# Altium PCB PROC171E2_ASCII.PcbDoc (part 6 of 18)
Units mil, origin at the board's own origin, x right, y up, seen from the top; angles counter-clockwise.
Board outline 7700 x 2300 mil, 6 copper layers (Top Layer, GND 1, SIG 1, SIG 2, GND 2, Bottom Layer), stack 61.062 mil thick; 938 components, 688 nets, 11933 pads, 1723 vias.
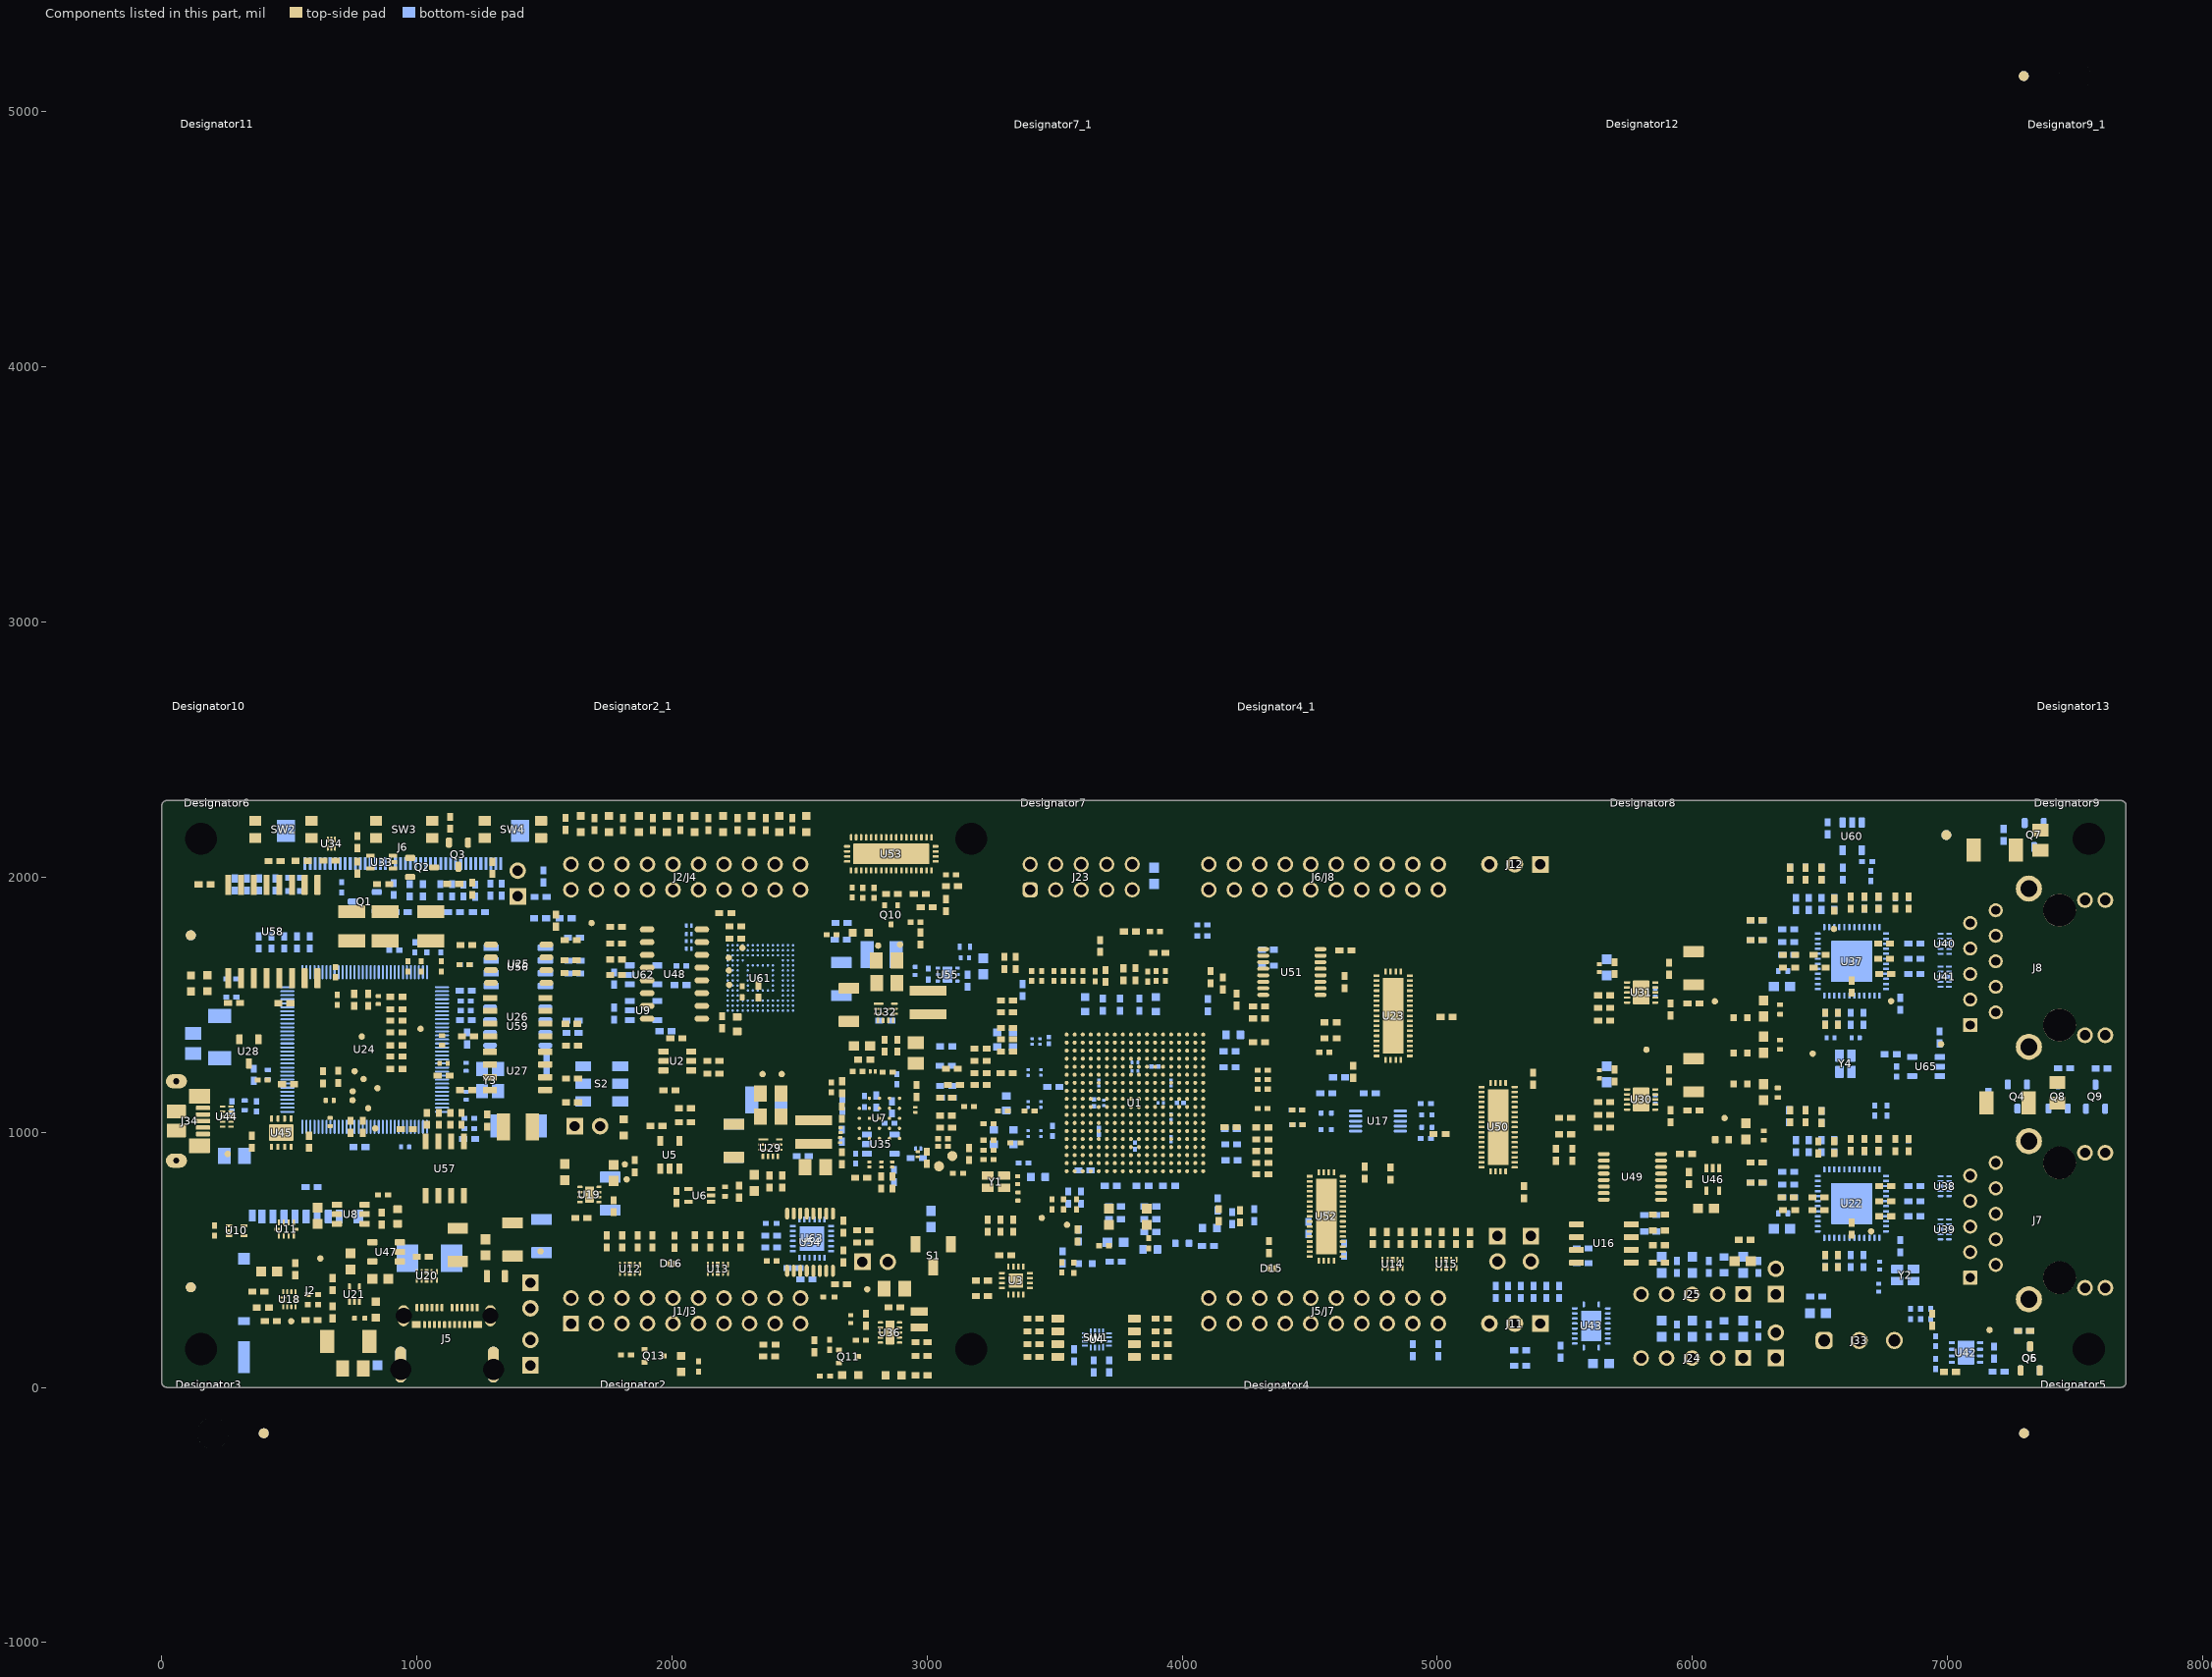
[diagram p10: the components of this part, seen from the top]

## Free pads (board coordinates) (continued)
  round 1 on Mech23: 1(4219.17,1490) 1(4219.17,1490) 1(4219.17,1570) 1(4219.17,1570) 1(4219.17,1575) 1(4219.17,1575) 1(4219.17,1585) 1(4219.17,1585) 1(4219.17,1590) 1(4219.17,1590) 1(4219.17,1670) 1(4219.17,1670) 1(4219.17,1675) 1(4219.17,1675) 1(4219.17,1685) 1(4219.17,1685) 1(4219.17,1690) 1(4219.17,1690) 1(4220.17,620) 1(4220.17,620) 1(4220.17,720) 1(4220.17,720) 1(4220.17,820) 1(4220.17,820) 1(4220.17,920) 1(4220.17,920) 1(4220.17,1020) 1(4220.17,1020) 1(4220.17,1280) 1(4220.17,1280) 1(4220.17,1380) 1(4220.17,1380) 1(4220.17,1480) 1(4220.17,1480) 1(4220.17,1580) 1(4220.17,1580) 1(4220.17,1680) 1(4220.17,1680) 1(4224.17,620) 1(4224.17,620) 1(4224.17,720) 1(4224.17,720) 1(4224.17,820) 1(4224.17,820) 1(4224.17,920) 1(4224.17,920) 1(4224.17,1020) 1(4224.17,1020) 1(4224.17,1280) 1(4224.17,1280) 1(4224.17,1380) 1(4224.17,1380) 1(4224.17,1480) 1(4224.17,1480) 1(4224.17,1580) 1(4224.17,1580) 1(4224.17,1680) 1(4224.17,1680) 1(4294.17,240) 1(4294.17,240) 1(4294.17,260) 1(4294.17,260) 1(4294.17,340) 1(4294.17,340) 1(4294.17,360) 1(4294.17,360) 1(4294.17,1940) 1(4294.17,1940) 1(4294.17,1960) 1(4294.17,1960) 1(4294.17,2040) 1(4294.17,2040) 1(4294.17,2060) 1(4294.17,2060) 1(4298.17,244) 1(4298.17,244) 1(4298.17,256) 1(4298.17,256) 1(4298.17,344) 1(4298.17,344) 1(4298.17,356) 1(4298.17,356) 1(4298.17,1944) 1(4298.17,1944) 1(4298.17,1956) 1(4298.17,1956) 1(4298.17,2044) 1(4298.17,2044) 1(4298.17,2056) 1(4298.17,2056) 1(4310.17,244) 1(4310.17,244) 1(4310.17,256) 1(4310.17,256) 1(4310.17,344) 1(4310.17,344) 1(4310.17,356) 1(4310.17,356) 1(4310.17,1944) 1(4310.17,1944) 1(4310.17,1956) 1(4310.17,1956) 1(4310.17,2044) 1(4310.17,2044) 1(4310.17,2056) 1(4310.17,2056) 1(4314.17,240) 1(4314.17,240) 1(4314.17,260) 1(4314.17,260) 1(4314.17,340) 1(4314.17,340) 1(4314.17,360) 1(4314.17,360) 1(4314.17,1940) 1(4314.17,1940) 1(4314.17,1960) 1(4314.17,1960) 1(4314.17,2040) 1(4314.17,2040) 1(4314.17,2060) 1(4314.17,2060) 1(4329.17,1080) 1(4329.17,1084) 1(4329.17,1096) 1(4329.17,1100) 1(4339.17,620) 1(4339.17,620) 1(4339.17,720) 1(4339.17,720) 1(4339.17,820) 1(4339.17,820) 1(4339.17,920) 1(4339.17,920) 1(4339.17,1020) 1(4339.17,1020) 1(4339.17,1280) 1(4339.17,1280) 1(4339.17,1380) 1(4339.17,1380) 1(4339.17,1480) 1(4339.17,1480) 1(4339.17,1580) 1(4339.17,1580) 1(4339.17,1680) 1(4339.17,1680) 1(4343.17,620) 1(4343.17,620) 1(4343.17,720) 1(4343.17,720) 1(4343.17,820) 1(4343.17,820) 1(4343.17,920) 1(4343.17,920) 1(4343.17,1020) 1(4343.17,1020) 1(4343.17,1280) 1(4343.17,1280) 1(4343.17,1380) 1(4343.17,1380) 1(4343.17,1480) 1(4343.17,1480) 1(4343.17,1580) 1(4343.17,1580) 1(4343.17,1680) 1(4343.17,1680) 1(4344.17,610) 1(4344.17,610) 1(4344.17,615) 1(4344.17,615) 1(4344.17,625) 1(4344.17,625) 1(4344.17,630) 1(4344.17,630) 1(4344.17,710) 1(4344.17,710) 1(4344.17,715) 1(4344.17,715) 1(4344.17,725) 1(4344.17,725) 1(4344.17,730) 1(4344.17,730) 1(4344.17,810) 1(4344.17,810) 1(4344.17,815) 1(4344.17,815) 1(4344.17,825) 1(4344.17,825) 1(4344.17,830) 1(4344.17,830) 1(4344.17,910) 1(4344.17,910) 1(4344.17,915) 1(4344.17,915) 1(4344.17,925) 1(4344.17,925) 1(4344.17,930) 1(4344.17,930) 1(4344.17,1010) 1(4344.17,1010) 1(4344.17,1015) 1(4344.17,1015) 1(4344.17,1025) 1(4344.17,1025) 1(4344.17,1030) 1(4344.17,1030) 1(4344.17,1270) 1(4344.17,1270) 1(4344.17,1275) 1(4344.17,1275) 1(4344.17,1285) 1(4344.17,1285) 1(4344.17,1290) 1(4344.17,1290) 1(4344.17,1370) 1(4344.17,1370) 1(4344.17,1375) 1(4344.17,1375) 1(4344.17,1385) 1(4344.17,1385) 1(4344.17,1390) 1(4344.17,1390) 1(4344.17,1470) 1(4344.17,1470) 1(4344.17,1475) 1(4344.17,1475) 1(4344.17,1485) 1(4344.17,1485) 1(4344.17,1490) 1(4344.17,1490) 1(4344.17,1570) 1(4344.17,1570) 1(4344.17,1575) 1(4344.17,1575) 1(4344.17,1585) 1(4344.17,1585) 1(4344.17,1590) 1(4344.17,1590) 1(4344.17,1670) 1(4344.17,1670) 1(4344.17,1675) 1(4344.17,1675) 1(4344.17,1685) 1(4344.17,1685) 1(4344.17,1690) 1(4344.17,1690) 1(4346.17,614) 1(4346.17,614) 1(4346.17,617) 1(4346.17,617) 1(4346.17,623) 1(4346.17,623) 1(4346.17,626) 1(4346.17,626) 1(4346.17,714) 1(4346.17,714) 1(4346.17,717) 1(4346.17,717) 1(4346.17,723) 1(4346.17,723) 1(4346.17,726) 1(4346.17,726) 1(4346.17,814) 1(4346.17,814) 1(4346.17,817) 1(4346.17,817) 1(4346.17,823) 1(4346.17,823) 1(4346.17,826) 1(4346.17,826) 1(4346.17,914) 1(4346.17,914) 1(4346.17,917) 1(4346.17,917) 1(4346.17,923) 1(4346.17,923) 1(4346.17,926) 1(4346.17,926) 1(4346.17,1014) 1(4346.17,1014) 1(4346.17,1017) 1(4346.17,1017) 1(4346.17,1023) 1(4346.17,1023) 1(4346.17,1026) 1(4346.17,1026) 1(4346.17,1274) 1(4346.17,1274) 1(4346.17,1277) 1(4346.17,1277) 1(4346.17,1283) 1(4346.17,1283) 1(4346.17,1286) 1(4346.17,1286) 1(4346.17,1374) 1(4346.17,1374) 1(4346.17,1377) 1(4346.17,1377) 1(4346.17,1383) 1(4346.17,1383) 1(4346.17,1386) 1(4346.17,1386) 1(4346.17,1474) 1(4346.17,1474) 1(4346.17,1477) 1(4346.17,1477) 1(4346.17,1483) 1(4346.17,1483) 1(4346.17,1486) 1(4346.17,1486) 1(4346.17,1574) 1(4346.17,1574) 1(4346.17,1577) 1(4346.17,1577) 1(4346.17,1583) 1(4346.17,1583) 1(4346.17,1586) 1(4346.17,1586) 1(4346.17,1674) 1(4346.17,1674) 1(4346.17,1677) 1(4346.17,1677) 1(4346.17,1683) 1(4346.17,1683) 1(4346.17,1686) 1(4346.17,1686) 1(4349.17,615) 1(4349.17,615) 1(4349.17,617) 1(4349.17,617) 1(4349.17,623) 1(4349.17,623) 1(4349.17,625) 1(4349.17,625) 1(4349.17,715) 1(4349.17,715) 1(4349.17,717) 1(4349.17,717) 1(4349.17,723) 1(4349.17,723) 1(4349.17,725) 1(4349.17,725) 1(4349.17,815) 1(4349.17,815) 1(4349.17,817) 1(4349.17,817) 1(4349.17,823) 1(4349.17,823) 1(4349.17,825) 1(4349.17,825) 1(4349.17,915) 1(4349.17,915) 1(4349.17,917) 1(4349.17,917) 1(4349.17,923) 1(4349.17,923) 1(4349.17,925) 1(4349.17,925) 1(4349.17,1015) 1(4349.17,1015) 1(4349.17,1017) 1(4349.17,1017) 1(4349.17,1023) 1(4349.17,1023) 1(4349.17,1025) 1(4349.17,1025) 1(4349.17,1275) 1(4349.17,1275) 1(4349.17,1277) 1(4349.17,1277) 1(4349.17,1283) 1(4349.17,1283) 1(4349.17,1285) 1(4349.17,1285) 1(4349.17,1375) 1(4349.17,1375) 1(4349.17,1377) 1(4349.17,1377) 1(4349.17,1383) 1(4349.17,1383) 1(4349.17,1385) 1(4349.17,1385) 1(4349.17,1475) 1(4349.17,1475) 1(4349.17,1477) 1(4349.17,1477) 1(4349.17,1483) 1(4349.17,1483) 1(4349.17,1485) 1(4349.17,1485) 1(4349.17,1575) 1(4349.17,1575) 1(4349.17,1577) 1(4349.17,1577) 1(4349.17,1583) 1(4349.17,1583) 1(4349.17,1585) 1(4349.17,1585) 1(4349.17,1675) 1(4349.17,1675) 1(4349.17,1677) 1(4349.17,1677) 1(4349.17,1683) 1(4349.17,1683) 1(4349.17,1685) 1(4349.17,1685) 1(4352.17,614) 1(4352.17,614) 1(4352.17,617) 1(4352.17,617) 1(4352.17,623) 1(4352.17,623) 1(4352.17,626) 1(4352.17,626) 1(4352.17,714) 1(4352.17,714) 1(4352.17,717) 1(4352.17,717) 1(4352.17,723) 1(4352.17,723) 1(4352.17,726) 1(4352.17,726) 1(4352.17,814) 1(4352.17,814) 1(4352.17,817) 1(4352.17,817) 1(4352.17,823) 1(4352.17,823) 1(4352.17,826) 1(4352.17,826) 1(4352.17,914) 1(4352.17,914) 1(4352.17,917) 1(4352.17,917) 1(4352.17,923) 1(4352.17,923) 1(4352.17,926) 1(4352.17,926) 1(4352.17,1014) 1(4352.17,1014) 1(4352.17,1017) 1(4352.17,1017) 1(4352.17,1023) 1(4352.17,1023) 1(4352.17,1026) 1(4352.17,1026) 1(4352.17,1274) 1(4352.17,1274) 1(4352.17,1277) 1(4352.17,1277) 1(4352.17,1283) 1(4352.17,1283) 1(4352.17,1286) 1(4352.17,1286) 1(4352.17,1374) 1(4352.17,1374) 1(4352.17,1377) 1(4352.17,1377) 1(4352.17,1383) 1(4352.17,1383) 1(4352.17,1386) 1(4352.17,1386) 1(4352.17,1474) 1(4352.17,1474) 1(4352.17,1477) 1(4352.17,1477) 1(4352.17,1483) 1(4352.17,1483) 1(4352.17,1486) 1(4352.17,1486) 1(4352.17,1574) 1(4352.17,1574) 1(4352.17,1577) 1(4352.17,1577) 1(4352.17,1583) 1(4352.17,1583) 1(4352.17,1586) 1(4352.17,1586) 1(4352.17,1674) 1(4352.17,1674) 1(4352.17,1677) 1(4352.17,1677) 1(4352.17,1683) 1(4352.17,1683) 1(4352.17,1686) 1(4352.17,1686) 1(4354.17,610) 1(4354.17,610) 1(4354.17,615) 1(4354.17,615) 1(4354.17,625) 1(4354.17,625) 1(4354.17,630) 1(4354.17,630) 1(4354.17,710) 1(4354.17,710) 1(4354.17,715) 1(4354.17,715) 1(4354.17,725) 1(4354.17,725) 1(4354.17,730) 1(4354.17,730) 1(4354.17,810) 1(4354.17,810) 1(4354.17,815) 1(4354.17,815) 1(4354.17,825) 1(4354.17,825) 1(4354.17,830) 1(4354.17,830) 1(4354.17,910) 1(4354.17,910) 1(4354.17,915) 1(4354.17,915) 1(4354.17,925) 1(4354.17,925) 1(4354.17,930) 1(4354.17,930) 1(4354.17,1010) 1(4354.17,1010) 1(4354.17,1015) 1(4354.17,1015) 1(4354.17,1025) 1(4354.17,1025) 1(4354.17,1030) 1(4354.17,1030) 1(4354.17,1270) 1(4354.17,1270) 1(4354.17,1275) 1(4354.17,1275) 1(4354.17,1285) 1(4354.17,1285) 1(4354.17,1290) 1(4354.17,1290) 1(4354.17,1370) 1(4354.17,1370) 1(4354.17,1375) 1(4354.17,1375) 1(4354.17,1385) 1(4354.17,1385) 1(4354.17,1390) 1(4354.17,1390) 1(4354.17,1470) 1(4354.17,1470) 1(4354.17,1475) 1(4354.17,1475) 1(4354.17,1485) 1(4354.17,1485) 1(4354.17,1490) 1(4354.17,1490) 1(4354.17,1570) 1(4354.17,1570) 1(4354.17,1575) 1(4354.17,1575) 1(4354.17,1585) 1(4354.17,1585) 1(4354.17,1590) 1(4354.17,1590) 1(4354.17,1670) 1(4354.17,1670) 1(4354.17,1675) 1(4354.17,1675) 1(4354.17,1685) 1(4354.17,1685) 1(4354.17,1690) 1(4354.17,1690) 1(4355.17,620) 1(4355.17,620) 1(4355.17,720) 1(4355.17,720) 1(4355.17,820) 1(4355.17,820) 1(4355.17,920) 1(4355.17,920) 1(4355.17,1020) 1(4355.17,1020) 1(4355.17,1280) 1(4355.17,1280) 1(4355.17,1380) 1(4355.17,1380) 1(4355.17,1480) 1(4355.17,1480) 1(4355.17,1580) 1(4355.17,1580) 1(4355.17,1680) 1(4355.17,1680) 1(4359.17,620) 1(4359.17,620) 1(4359.17,720) 1(4359.17,720) 1(4359.17,820) 1(4359.17,820) 1(4359.17,920) 1(4359.17,920) 1(4359.17,1020) 1(4359.17,1020) 1(4359.17,1280) 1(4359.17,1280) 1(4359.17,1380) 1(4359.17,1380) 1(4359.17,1480) 1(4359.17,1480) 1(4359.17,1580) 1(4359.17,1580) 1(4359.17,1680) 1(4359.17,1680) 1(4364.17,2240) 1(4364.17,2244) 1(4364.17,2256) 1(4364.17,2260) 1(4394.17,61.38) 1(4394.17,65.38) 1(4394.17,77.38) 1(4394.17,81.38) 1(4394.17,240) 1(4394.17,240) 1(4394.17,260) 1(4394.17,260) 1(4394.17,340) 1(4394.17,340) 1(4394.17,360) 1(4394.17,360) 1(4394.17,1940) 1(4394.17,1940) 1(4394.17,1960) 1(4394.17,1960) 1(4394.17,2040) 1(4394.17,2040) 1(4394.17,2060) 1(4394.17,2060) 1(4396.26,477.39) 1(4396.26,477.39) 1(4396.26,497.39) 1(4396.26,497.39) 1(4398.17,244) 1(4398.17,244) 1(4398.17,256) 1(4398.17,256) 1(4398.17,344) 1(4398.17,344) 1(4398.17,356) 1(4398.17,356) 1(4398.17,1944) 1(4398.17,1944) 1(4398.17,1956) 1(4398.17,1956) 1(4398.17,2044) 1(4398.17,2044) 1(4398.17,2056) 1(4398.17,2056) 1(4400.26,481.39) 1(4400.26,481.39) 1(4400.26,493.39) 1(4400.26,493.39) 1(4401.26,487.39) 1(4401.26,487.39) 1(4403.26,487.39) 1(4403.26,487.39) 1(4404.17,1805) 1(4404.17,1805) 1(4404.17,1825) 1(4404.17,1825) 1(4406.26,482.39) 1(4406.26,482.39) 1(4406.26,484.39) 1(4406.26,484.39) 1(4406.26,490.39) 1(4406.26,490.39) 1(4406.26,492.39) 1(4406.26,492.39) 1(4408.17,1809) 1(4408.17,1809) 1(4408.17,1821) 1(4408.17,1821) 1(4409.17,1815) 1(4409.17,1815) 1(4409.26,487.39) 1(4409.26,487.39) 1(4410.17,244) 1(4410.17,244) 1(4410.17,256) 1(4410.17,256) 1(4410.17,344) 1(4410.17,344) 1(4410.17,356) 1(4410.17,356) 1(4410.17,1944) 1(4410.17,1944) 1(4410.17,1956) 1(4410.17,1956) 1(4410.17,2044) 1(4410.17,2044) 1(4410.17,2056) 1(4410.17,2056) 1(4411.17,1815) 1(4411.17,1815) 1(4411.26,487.39) 1(4411.26,487.39) 1(4412.26,481.39) 1(4412.26,481.39) 1(4412.26,493.39) 1(4412.26,493.39) 1(4414.17,240) 1(4414.17,240) 1(4414.17,260) 1(4414.17,260) 1(4414.17,340) 1(4414.17,340) 1(4414.17,360) 1(4414.17,360) 1(4414.17,1810) 1(4414.17,1810) 1(4414.17,1812) 1(4414.17,1812) 1(4414.17,1818) 1(4414.17,1818) 1(4414.17,1820) 1(4414.17,1820) 1(4414.17,1940) 1(4414.17,1940) 1(4414.17,1960) 1(4414.17,1960) 1(4414.17,2040) 1(4414.17,2040) 1(4414.17,2060) 1(4414.17,2060) 1(4416.26,477.39) 1(4416.26,477.39) 1(4416.26,497.39) 1(4416.26,497.39) 1(4417.17,1815) 1(4417.17,1815) 1(4419.17,-116.65) 1(4419.17,-116.65) 1(4419.17,-96.65) 1(4419.17,-96.65) 1(4419.17,1815) 1(4419.17,1815) 1(4420.17,1809) 1(4420.17,1809) 1(4420.17,1821) 1(4420.17,1821) 1(4423.17,-112.65) 1(4423.17,-112.65) 1(4423.17,-100.65) 1(4423.17,-100.65) 1(4424.17,-106.65) 1(4424.17,-106.65) 1(4424.17,1805) 1(4424.17,1805) 1(4424.17,1825) 1(4424.17,1825) 1(4426.17,-106.65) 1(4426.17,-106.65) 1(4429.17,-111.65) 1(4429.17,-111.65) 1(4429.17,-109.65) 1(4429.17,-109.65) 1(4429.17,-103.65) 1(4429.17,-103.65) 1(4429.17,-101.65) 1(4429.17,-101.65) 1(4432.17,-106.65) 1(4432.17,-106.65) 1(4434.17,-106.65) 1(4434.17,-106.65) 1(4435.17,-112.65) 1(4435.17,-112.65) 1(4435.17,-100.65) 1(4435.17,-100.65) 1(4439.17,-116.65) 1(4439.17,-116.65) 1(4439.17,-96.65) 1(4439.17,-96.65) 1(4474.17,620) 1(4474.17,620) 1(4474.17,720) 1(4474.17,720) 1(4474.17,820) 1(4474.17,820) 1(4474.17,920) 1(4474.17,920) 1(4474.17,1020) 1(4474.17,1020) 1(4474.17,1280) 1(4474.17,1280) 1(4474.17,1380) 1(4474.17,1380) 1(4474.17,1480) 1(4474.17,1480) 1(4474.17,1580) 1(4474.17,1580) 1(4474.17,1680) 1(4474.17,1680) 1(4478.17,620) 1(4478.17,620) 1(4478.17,720) 1(4478.17,720) 1(4478.17,820) 1(4478.17,820) 1(4478.17,920) 1(4478.17,920) 1(4478.17,1020) 1(4478.17,1020) 1(4478.17,1280) 1(4478.17,1280) 1(4478.17,1380) 1(4478.17,1380) 1(4478.17,1480) 1(4478.17,1480) 1(4478.17,1580) 1(4478.17,1580) 1(4478.17,1680) 1(4478.17,1680) 1(4479.17,610) 1(4479.17,610) 1(4479.17,615) 1(4479.17,615) 1(4479.17,625) 1(4479.17,625) 1(4479.17,630) 1(4479.17,630) 1(4479.17,710) 1(4479.17,710) 1(4479.17,715) 1(4479.17,715) 1(4479.17,725) 1(4479.17,725) 1(4479.17,730) 1(4479.17,730) 1(4479.17,810) 1(4479.17,810) 1(4479.17,815) 1(4479.17,815) 1(4479.17,825) 1(4479.17,825) 1(4479.17,830) 1(4479.17,830) 1(4479.17,910) 1(4479.17,910) 1(4479.17,915) 1(4479.17,915) 1(4479.17,925) 1(4479.17,925) 1(4479.17,930) 1(4479.17,930) 1(4479.17,1010) 1(4479.17,1010) 1(4479.17,1015) 1(4479.17,1015) 1(4479.17,1025) 1(4479.17,1025) 1(4479.17,1030) 1(4479.17,1030) 1(4479.17,1270) 1(4479.17,1270) 1(4479.17,1275) 1(4479.17,1275) 1(4479.17,1285) 1(4479.17,1285) 1(4479.17,1290) 1(4479.17,1290) 1(4479.17,1370) 1(4479.17,1370) 1(4479.17,1375) 1(4479.17,1375) 1(4479.17,1385) 1(4479.17,1385) 1(4479.17,1390) 1(4479.17,1390) 1(4479.17,1470) 1(4479.17,1470) 1(4479.17,1475) 1(4479.17,1475) 1(4479.17,1485) 1(4479.17,1485) 1(4479.17,1490) 1(4479.17,1490) 1(4479.17,1570) 1(4479.17,1570) 1(4479.17,1575) 1(4479.17,1575) 1(4479.17,1585) 1(4479.17,1585) 1(4479.17,1590) 1(4479.17,1590) 1(4479.17,1670) 1(4479.17,1670) 1(4479.17,1675) 1(4479.17,1675) 1(4479.17,1685) 1(4479.17,1685) 1(4479.17,1690) 1(4479.17,1690) 1(4481.17,614) 1(4481.17,614) 1(4481.17,617) 1(4481.17,617) 1(4481.17,623) 1(4481.17,623) 1(4481.17,626) 1(4481.17,626) 1(4481.17,714) 1(4481.17,714) 1(4481.17,717) 1(4481.17,717) 1(4481.17,723) 1(4481.17,723) 1(4481.17,726) 1(4481.17,726) 1(4481.17,814) 1(4481.17,814) 1(4481.17,817) 1(4481.17,817) 1(4481.17,823) 1(4481.17,823) 1(4481.17,826) 1(4481.17,826) 1(4481.17,914) 1(4481.17,914) 1(4481.17,917) 1(4481.17,917) 1(4481.17,923) 1(4481.17,923) 1(4481.17,926) 1(4481.17,926) 1(4481.17,1014) 1(4481.17,1014) 1(4481.17,1017) 1(4481.17,1017) 1(4481.17,1023) 1(4481.17,1023) 1(4481.17,1026) 1(4481.17,1026) 1(4481.17,1274) 1(4481.17,1274) 1(4481.17,1277) 1(4481.17,1277) 1(4481.17,1283) 1(4481.17,1283) 1(4481.17,1286) 1(4481.17,1286) 1(4481.17,1374) 1(4481.17,1374) 1(4481.17,1377) 1(4481.17,1377) 1(4481.17,1383) 1(4481.17,1383) 1(4481.17,1386) 1(4481.17,1386) 1(4481.17,1474) 1(4481.17,1474) 1(4481.17,1477) 1(4481.17,1477) 1(4481.17,1483) 1(4481.17,1483) 1(4481.17,1486) 1(4481.17,1486) 1(4481.17,1574) 1(4481.17,1574) 1(4481.17,1577) 1(4481.17,1577) 1(4481.17,1583) 1(4481.17,1583) 1(4481.17,1586) 1(4481.17,1586) 1(4481.17,1674) 1(4481.17,1674) 1(4481.17,1677) 1(4481.17,1677) 1(4481.17,1683) 1(4481.17,1683) 1(4481.17,1686) 1(4481.17,1686) 1(4484.17,615) 1(4484.17,615) 1(4484.17,617) 1(4484.17,617) 1(4484.17,623) 1(4484.17,623) 1(4484.17,625) 1(4484.17,625) 1(4484.17,715) 1(4484.17,715) 1(4484.17,717) 1(4484.17,717) 1(4484.17,723) 1(4484.17,723) 1(4484.17,725) 1(4484.17,725) 1(4484.17,815) 1(4484.17,815) 1(4484.17,817) 1(4484.17,817) 1(4484.17,823) 1(4484.17,823) 1(4484.17,825) 1(4484.17,825) 1(4484.17,915) 1(4484.17,915) 1(4484.17,917) 1(4484.17,917) 1(4484.17,923) 1(4484.17,923) 1(4484.17,925) 1(4484.17,925) 1(4484.17,1015) 1(4484.17,1015) 1(4484.17,1017) 1(4484.17,1017) 1(4484.17,1023) 1(4484.17,1023) 1(4484.17,1025) 1(4484.17,1025) 1(4484.17,1275) 1(4484.17,1275) 1(4484.17,1277) 1(4484.17,1277) 1(4484.17,1283) 1(4484.17,1283) 1(4484.17,1285) 1(4484.17,1285) 1(4484.17,1375) 1(4484.17,1375) 1(4484.17,1377) 1(4484.17,1377) 1(4484.17,1383) 1(4484.17,1383) 1(4484.17,1385) 1(4484.17,1385) 1(4484.17,1475) 1(4484.17,1475) 1(4484.17,1477) 1(4484.17,1477) 1(4484.17,1483) 1(4484.17,1483) 1(4484.17,1485) 1(4484.17,1485) 1(4484.17,1575) 1(4484.17,1575) 1(4484.17,1577) 1(4484.17,1577) 1(4484.17,1583) 1(4484.17,1583) 1(4484.17,1585) 1(4484.17,1585) 1(4484.17,1675) 1(4484.17,1675) 1(4484.17,1677) 1(4484.17,1677) 1(4484.17,1683) 1(4484.17,1683) 1(4484.17,1685) 1(4484.17,1685) 1(4487.17,614) 1(4487.17,614) 1(4487.17,617) 1(4487.17,617) 1(4487.17,623) 1(4487.17,623) 1(4487.17,626) 1(4487.17,626) 1(4487.17,714) 1(4487.17,714) 1(4487.17,717) 1(4487.17,717) 1(4487.17,723) 1(4487.17,723) 1(4487.17,726) 1(4487.17,726) 1(4487.17,814) 1(4487.17,814) 1(4487.17,817) 1(4487.17,817) 1(4487.17,823) 1(4487.17,823) 1(4487.17,826) 1(4487.17,826) 1(4487.17,914) 1(4487.17,914) 1(4487.17,917) 1(4487.17,917) 1(4487.17,923) 1(4487.17,923) 1(4487.17,926) 1(4487.17,926) 1(4487.17,1014) 1(4487.17,1014) 1(4487.17,1017) 1(4487.17,1017) 1(4487.17,1023) 1(4487.17,1023) 1(4487.17,1026) 1(4487.17,1026) 1(4487.17,1274) 1(4487.17,1274) 1(4487.17,1277) 1(4487.17,1277) 1(4487.17,1283) 1(4487.17,1283) 1(4487.17,1286) 1(4487.17,1286) 1(4487.17,1374) 1(4487.17,1374) 1(4487.17,1377) 1(4487.17,1377) 1(4487.17,1383) 1(4487.17,1383) 1(4487.17,1386) 1(4487.17,1386) 1(4487.17,1474) 1(4487.17,1474) 1(4487.17,1477) 1(4487.17,1477) 1(4487.17,1483) 1(4487.17,1483) 1(4487.17,1486) 1(4487.17,1486) 1(4487.17,1574) 1(4487.17,1574) 1(4487.17,1577) 1(4487.17,1577) 1(4487.17,1583) 1(4487.17,1583) 1(4487.17,1586) 1(4487.17,1586) 1(4487.17,1674) 1(4487.17,1674) 1(4487.17,1677) 1(4487.17,1677) 1(4487.17,1683) 1(4487.17,1683) 1(4487.17,1686) 1(4487.17,1686) 1(4489.17,610) 1(4489.17,610) 1(4489.17,615) 1(4489.17,615) 1(4489.17,625) 1(4489.17,625) 1(4489.17,630) 1(4489.17,630) 1(4489.17,710) 1(4489.17,710) 1(4489.17,715) 1(4489.17,715) 1(4489.17,725) 1(4489.17,725) 1(4489.17,730) 1(4489.17,730) 1(4489.17,810) 1(4489.17,810) 1(4489.17,815) 1(4489.17,815) 1(4489.17,825) 1(4489.17,825) 1(4489.17,830) 1(4489.17,830) 1(4489.17,910) 1(4489.17,910) 1(4489.17,915) 1(4489.17,915) 1(4489.17,925) 1(4489.17,925) 1(4489.17,930) 1(4489.17,930) 1(4489.17,1010) 1(4489.17,1010) 1(4489.17,1015) 1(4489.17,1015) 1(4489.17,1025) 1(4489.17,1025) 1(4489.17,1030) 1(4489.17,1030) 1(4489.17,1270) 1(4489.17,1270) 1(4489.17,1275) 1(4489.17,1275) 1(4489.17,1285) 1(4489.17,1285) 1(4489.17,1290) 1(4489.17,1290) 1(4489.17,1370) 1(4489.17,1370) 1(4489.17,1375) 1(4489.17,1375) 1(4489.17,1385) 1(4489.17,1385) 1(4489.17,1390) 1(4489.17,1390) 1(4489.17,1470) 1(4489.17,1470) 1(4489.17,1475) 1(4489.17,1475) 1(4489.17,1485) 1(4489.17,1485) 1(4489.17,1490) 1(4489.17,1490) 1(4489.17,1570) 1(4489.17,1570) 1(4489.17,1575) 1(4489.17,1575) 1(4489.17,1585) 1(4489.17,1585) 1(4489.17,1590) 1(4489.17,1590) 1(4489.17,1670) 1(4489.17,1670) 1(4489.17,1675) 1(4489.17,1675) 1(4489.17,1685) 1(4489.17,1685) 1(4489.17,1690) 1(4489.17,1690) 1(4490.17,620) 1(4490.17,620) 1(4490.17,720) 1(4490.17,720) 1(4490.17,820) 1(4490.17,820) 1(4490.17,920) 1(4490.17,920) 1(4490.17,1020) 1(4490.17,1020) 1(4490.17,1280) 1(4490.17,1280) 1(4490.17,1380) 1(4490.17,1380) 1(4490.17,1480) 1(4490.17,1480) 1(4490.17,1580) 1(4490.17,1580) 1(4490.17,1680) 1(4490.17,1680) 1(4494.17,240) 1(4494.17,240) 1(4494.17,260) 1(4494.17,260) 1(4494.17,340) 1(4494.17,340) 1(4494.17,360) 1(4494.17,360) 1(4494.17,620) 1(4494.17,620) 1(4494.17,720) 1(4494.17,720) 1(4494.17,820) 1(4494.17,820) 1(4494.17,920) 1(4494.17,920) 1(4494.17,1020) 1(4494.17,1020) 1(4494.17,1280) 1(4494.17,1280) 1(4494.17,1380) 1(4494.17,1380) 1(4494.17,1480) 1(4494.17,1480) 1(4494.17,1580) 1(4494.17,1580) 1(4494.17,1680) 1(4494.17,1680) 1(4494.17,1940) 1(4494.17,1940) 1(4494.17,1960) 1(4494.17,1960) 1(4494.17,2040) 1(4494.17,2040) 1(4494.17,2060) 1(4494.17,2060) 1(4498.17,244) 1(4498.17,244) 1(4498.17,256) 1(4498.17,256) 1(4498.17,344) 1(4498.17,344) 1(4498.17,356) 1(4498.17,356) 1(4498.17,1944) 1(4498.17,1944) 1(4498.17,1956) 1(4498.17,1956) 1(4498.17,2044) 1(4498.17,2044) 1(4498.17,2056) 1(4498.17,2056) 1(4510.17,244) 1(4510.17,244) 1(4510.17,256) 1(4510.17,256) 1(4510.17,344) 1(4510.17,344) 1(4510.17,356) 1(4510.17,356) 1(4510.17,1944) 1(4510.17,1944) 1(4510.17,1956) 1(4510.17,1956) 1(4510.17,2044) 1(4510.17,2044) 1(4510.17,2056) 1(4510.17,2056) 1(4514.17,240) 1(4514.17,240) 1(4514.17,260) 1(4514.17,260) 1(4514.17,340) 1(4514.17,340) 1(4514.17,360) 1(4514.17,360) 1(4514.17,1940) 1(4514.17,1940) 1(4514.17,1960) 1(4514.17,1960) 1(4514.17,2040) 1(4514.17,2040) 1(4514.17,2060) 1(4514.17,2060) 1(4534.17,1065) 1(4534.17,1069) 1(4534.17,1081) 1(4534.17,1085) 1(4564.17,685) 1(4564.17,685) 1(4564.17,690) 1(4564.17,690) 1(4564.17,700) 1(4564.17,700) 1(4564.17,705) 1(4564.17,705) 1(4564.17,905) 1(4564.17,905) 1(4564.17,910) 1(4564.17,910) 1(4564.17,920) 1(4564.17,920) 1(4564.17,925) 1(4564.17,925) 1(4568.17,689) 1(4568.17,689) 1(4568.17,692) 1(4568.17,692) 1(4568.17,698) 1(4568.17,698) 1(4568.17,701) 1(4568.17,701) 1(4568.17,909) 1(4568.17,909) 1(4568.17,912) 1(4568.17,912) 1(4568.17,918) 1(4568.17,918) 1(4568.17,921) 1(4568.17,921) 1(4569.17,685) 1(4569.17,685) 1(4569.17,695) 1(4569.17,695) 1(4569.17,705) 1(4569.17,705) 1(4569.17,905) 1(4569.17,905) 1(4569.17,915) 1(4569.17,915) 1(4569.17,925) 1(4569.17,925) 1(4569.17,1075) 1(4569.17,1079) 1(4569.17,1091) 1(4569.17,1095) 1(4571.17,689) 1(4571.17,689) 1(4571.17,695) 1(4571.17,695) 1(4571.17,701) 1(4571.17,701) 1(4571.17,909) 1(4571.17,909) 1(4571.17,915) 1(4571.17,915) 1(4571.17,921) 1(4571.17,921) 1(4574.17,485) 1(4574.17,489) 1(4574.17,501) 1(4574.17,505) 1(4574.17,690) 1(4574.17,690) 1(4574.17,692) 1(4574.17,692) 1(4574.17,698) 1(4574.17,698) 1(4574.17,700) 1(4574.17,700) 1(4574.17,910) 1(4574.17,910) 1(4574.17,912) 1(4574.17,912) 1(4574.17,918) 1(4574.17,918) 1(4574.17,920) 1(4574.17,920) 1(4577.17,689) 1(4577.17,689) 1(4577.17,695) 1(4577.17,695) 1(4577.17,701) 1(4577.17,701) 1(4577.17,909) 1(4577.17,909) 1(4577.17,915) 1(4577.17,915) 1(4577.17,921) 1(4577.17,921) 1(4579.17,685) 1(4579.17,685) 1(4579.17,695) 1(4579.17,695) 1(4579.17,705) 1(4579.17,705) 1(4579.17,905) 1(4579.17,905) 1(4579.17,915) 1(4579.17,915) 1(4579.17,925) 1(4579.17,925) 1(4580.17,689) 1(4580.17,689) 1(4580.17,692) 1(4580.17,692) 1(4580.17,698) 1(4580.17,698) 1(4580.17,701) 1(4580.17,701) 1(4580.17,909) 1(4580.17,909) 1(4580.17,912) 1(4580.17,912) 1(4580.17,918) 1(4580.17,918) 1(4580.17,921) 1(4580.17,921) 1(4584.17,685) 1(4584.17,685) 1(4584.17,690) 1(4584.17,690) 1(4584.17,700) 1(4584.17,700) 1(4584.17,705) 1(4584.17,705) 1(4584.17,905) 1(4584.17,905) 1(4584.17,910) 1(4584.17,910) 1(4584.17,920) 1(4584.17,920) 1(4584.17,925) 1(4584.17,925) 1(4594.17,240) 1(4594.17,240) 1(4594.17,260) 1(4594.17,260) 1(4594.17,340) 1(4594.17,340) 1(4594.17,360) 1(4594.17,360) 1(4594.17,1300) 1(4594.17,1304) 1(4594.17,1316) 1(4594.17,1320) 1(4594.17,1940) 1(4594.17,1940) 1(4594.17,1960) 1(4594.17,1960) 1(4594.17,2040) 1(4594.17,2040) 1(4594.17,2060) 1(4594.17,2060) 1(4598.17,244) 1(4598.17,244) 1(4598.17,256) 1(4598.17,256) 1(4598.17,344) 1(4598.17,344) 1(4598.17,356) 1(4598.17,356) 1(4598.17,1944) 1(4598.17,1944) 1(4598.17,1956) 1(4598.17,1956) 1(4598.17,2044) 1(4598.17,2044) 1(4598.17,2056) 1(4598.17,2056) 1(4610.17,244) 1(4610.17,244) 1(4610.17,256) 1(4610.17,256) 1(4610.17,344) 1(4610.17,344) 1(4610.17,356) 1(4610.17,356) 1(4610.17,1944) 1(4610.17,1944) 1(4610.17,1956) 1(4610.17,1956) 1(4610.17,2044) 1(4610.17,2044) 1(4610.17,2056) 1(4610.17,2056) 1(4614.17,240) 1(4614.17,240) 1(4614.17,260) 1(4614.17,260) 1(4614.17,340) 1(4614.17,340) 1(4614.17,360) 1(4614.17,360) 1(4614.17,1940) 1(4614.17,1940) 1(4614.17,1960) 1(4614.17,1960) 1(4614.17,2040) 1(4614.17,2040) 1(4614.17,2060) 1(4614.17,2060) 1(4624.17,1324) 1(4624.17,1328) 1(4624.17,1340) 1(4624.17,1344) 1(4639.17,1635.49) 1(4639.17,1635.49) 1(4639.17,1640.49) 1(4639.17,1640.49) 1(4639.17,1650.49) 1(4639.17,1650.49) 1(4639.17,1655.49) 1(4639.17,1655.49) 1(4639.17,1690) 1(4639.17,1690) 1(4639.17,1695) 1(4639.17,1695) 1(4639.17,1705) 1(4639.17,1705) 1(4639.17,1710) 1(4639.17,1710) 1(4639.48,1576.1) 1(4639.48,1576.1) 1(4639.48,1581.1) 1(4639.48,1581.1) 1(4639.48,1591.1) 1(4639.48,1591.1) 1(4639.48,1596.1) 1(4639.48,1596.1) 1(4643.17,1639.49) 1(4643.17,1639.49) 1(4643.17,1642.49) 1(4643.17,1642.49) 1(4643.17,1648.49) 1(4643.17,1648.49) 1(4643.17,1651.49) 1(4643.17,1651.49) 1(4643.17,1694) 1(4643.17,1694) 1(4643.17,1697) 1(4643.17,1697) 1(4643.17,1703) 1(4643.17,1703) 1(4643.17,1706) 1(4643.17,1706) 1(4643.48,1580.1) 1(4643.48,1580.1) 1(4643.48,1583.1) 1(4643.48,1583.1) 1(4643.48,1589.1) 1(4643.48,1589.1) 1(4643.48,1592.1) 1(4643.48,1592.1) 1(4644.17,1635.49) 1(4644.17,1635.49) 1(4644.17,1645.49) 1(4644.17,1645.49) 1(4644.17,1655.49) 1(4644.17,1655.49) 1(4644.17,1690) 1(4644.17,1690) 1(4644.17,1700) 1(4644.17,1700) 1(4644.17,1710) 1(4644.17,1710) 1(4644.48,1576.1) 1(4644.48,1576.1) 1(4644.48,1586.1) 1(4644.48,1586.1) 1(4644.48,1596.1) 1(4644.48,1596.1) 1(4646.17,1405) 1(4646.17,1409) 1(4646.17,1421) 1(4646.17,1425) 1(4646.17,1639.49) 1(4646.17,1639.49) 1(4646.17,1645.49) 1(4646.17,1645.49) 1(4646.17,1651.49) 1(4646.17,1651.49) 1(4646.17,1694) 1(4646.17,1694) 1(4646.17,1700) 1(4646.17,1700) 1(4646.17,1706) 1(4646.17,1706) 1(4646.48,1580.1) 1(4646.48,1580.1) 1(4646.48,1586.1) 1(4646.48,1586.1) 1(4646.48,1592.1) 1(4646.48,1592.1) 1(4649.17,1640.49) 1(4649.17,1640.49) 1(4649.17,1642.49) 1(4649.17,1642.49) 1(4649.17,1648.49) 1(4649.17,1648.49) 1(4649.17,1650.49) 1(4649.17,1650.49) 1(4649.17,1695) 1(4649.17,1695) 1(4649.17,1697) 1(4649.17,1697) 1(4649.17,1703) 1(4649.17,1703) 1(4649.17,1705) 1(4649.17,1705) 1(4649.48,1581.1) 1(4649.48,1581.1) 1(4649.48,1583.1) 1(4649.48,1583.1) 1(4649.48,1589.1) 1(4649.48,1589.1) 1(4649.48,1591.1) 1(4649.48,1591.1) 1(4652.17,1639.49) 1(4652.17,1639.49) 1(4652.17,1645.49) 1(4652.17,1645.49) 1(4652.17,1651.49) 1(4652.17,1651.49) 1(4652.17,1694) 1(4652.17,1694) 1(4652.17,1700) 1(4652.17,1700) 1(4652.17,1706) 1(4652.17,1706) 1(4652.48,1580.1) 1(4652.48,1580.1) 1(4652.48,1586.1) 1(4652.48,1586.1) 1(4652.48,1592.1) 1(4652.48,1592.1) 1(4653.38,700.79) 1(4653.38,700.79) 1(4653.38,705.79) 1(4653.38,705.79) 1(4653.38,715.79) 1(4653.38,715.79) 1(4653.38,720.79) 1(4653.38,720.79) 1(4654.17,470) 1(4654.17,470) 1(4654.17,475) 1(4654.17,475) 1(4654.17,485) 1(4654.17,485) 1(4654.17,490) 1(4654.17,490) 1(4654.17,930) 1(4654.17,930) 1(4654.17,935) 1(4654.17,935) 1(4654.17,945) 1(4654.17,945) 1(4654.17,950) 1(4654.17,950) 1(4654.17,1635.49) 1(4654.17,1635.49) 1(4654.17,1645.49) 1(4654.17,1645.49) 1(4654.17,1655.49) 1(4654.17,1655.49) 1(4654.17,1690) 1(4654.17,1690) 1(4654.17,1700) 1(4654.17,1700) 1(4654.17,1710) 1(4654.17,1710) 1(4654.48,1576.1) 1(4654.48,1576.1) 1(4654.48,1586.1) 1(4654.48,1586.1) 1(4654.48,1596.1) 1(4654.48,1596.1) 1(4655.17,1639.49) 1(4655.17,1639.49) 1(4655.17,1642.49) 1(4655.17,1642.49) 1(4655.17,1648.49) 1(4655.17,1648.49) 1(4655.17,1651.49) 1(4655.17,1651.49) 1(4655.17,1694) 1(4655.17,1694) 1(4655.17,1697) 1(4655.17,1697) 1(4655.17,1703) 1(4655.17,1703) 1(4655.17,1706) 1(4655.17,1706) 1(4655.48,1580.1) 1(4655.48,1580.1) 1(4655.48,1583.1) 1(4655.48,1583.1) 1(4655.48,1589.1) 1(4655.48,1589.1) 1(4655.48,1592.1) 1(4655.48,1592.1) 1(4657.38,704.79) 1(4657.38,704.79) 1(4657.38,707.79) 1(4657.38,707.79) 1(4657.38,713.79) 1(4657.38,713.79) 1(4657.38,716.79) 1(4657.38,716.79) 1(4658.17,474) 1(4658.17,474) 1(4658.17,477) 1(4658.17,477) 1(4658.17,483) 1(4658.17,483) 1(4658.17,486) 1(4658.17,486) 1(4658.17,934) 1(4658.17,934) 1(4658.17,937) 1(4658.17,937) 1(4658.17,943) 1(4658.17,943) 1(4658.17,946) 1(4658.17,946) 1(4658.38,700.79) 1(4658.38,700.79) 1(4658.38,710.79) 1(4658.38,710.79) 1(4658.38,720.79) 1(4658.38,720.79) 1(4659.17,470) 1(4659.17,470) 1(4659.17,480) 1(4659.17,480) 1(4659.17,490) 1(4659.17,490) 1(4659.17,930) 1(4659.17,930) 1(4659.17,940) 1(4659.17,940) 1(4659.17,950) 1(4659.17,950) 1(4659.17,1635.49) 1(4659.17,1635.49) 1(4659.17,1640.49) 1(4659.17,1640.49) 1(4659.17,1650.49) 1(4659.17,1650.49) 1(4659.17,1655.49) 1(4659.17,1655.49) 1(4659.17,1690) 1(4659.17,1690) 1(4659.17,1695) 1(4659.17,1695) 1(4659.17,1705) 1(4659.17,1705) 1(4659.17,1710) 1(4659.17,1710) 1(4659.48,1576.1) 1(4659.48,1576.1) 1(4659.48,1581.1) 1(4659.48,1581.1) 1(4659.48,1591.1) 1(4659.48,1591.1) 1(4659.48,1596.1) 1(4659.48,1596.1) 1(4660.38,704.79) 1(4660.38,704.79) 1(4660.38,710.79) 1(4660.38,710.79) 1(4660.38,716.79) 1(4660.38,716.79) 1(4661.17,474) 1(4661.17,474) 1(4661.17,480) 1(4661.17,480) 1(4661.17,486) 1(4661.17,486) 1(4661.17,934) 1(4661.17,934) 1(4661.17,940) 1(4661.17,940) 1(4661.17,946) 1(4661.17,946) 1(4663.38,705.79) 1(4663.38,705.79) 1(4663.38,707.79) 1(4663.38,707.79) 1(4663.38,713.79) 1(4663.38,713.79) 1(4663.38,715.79) 1(4663.38,715.79) 1(4664.17,475) 1(4664.17,475) 1(4664.17,477) 1(4664.17,477) 1(4664.17,483) 1(4664.17,483) 1(4664.17,485) 1(4664.17,485) 1(4664.17,935) 1(4664.17,935) 1(4664.17,937) 1(4664.17,937) 1(4664.17,943) 1(4664.17,943) 1(4664.17,945) 1(4664.17,945) 1(4666.38,704.79) 1(4666.38,704.79) 1(4666.38,710.79) 1(4666.38,710.79) 1(4666.38,716.79) 1(4666.38,716.79) 1(4667.17,474) 1(4667.17,474) 1(4667.17,480) 1(4667.17,480) 1(4667.17,486) 1(4667.17,486) 1(4667.17,934) 1(4667.17,934) 1(4667.17,940) 1(4667.17,940) 1(4667.17,946) 1(4667.17,946) 1(4668.38,700.79) 1(4668.38,700.79) 1(4668.38,710.79) 1(4668.38,710.79) 1(4668.38,720.79) 1(4668.38,720.79) 1(4669.17,470) 1(4669.17,470) 1(4669.17,480) 1(4669.17,480) 1(4669.17,490) 1(4669.17,490) 1(4669.17,930) 1(4669.17,930) 1(4669.17,940) 1(4669.17,940) 1(4669.17,950) 1(4669.17,950) 1(4669.38,704.79) 1(4669.38,704.79) 1(4669.38,707.79) 1(4669.38,707.79) 1(4669.38,713.79) 1(4669.38,713.79) 1(4669.38,716.79) 1(4669.38,716.79) 1(4670.17,474) 1(4670.17,474) 1(4670.17,477) 1(4670.17,477) 1(4670.17,483) 1(4670.17,483) 1(4670.17,486) 1(4670.17,486) 1(4670.17,934) 1(4670.17,934) 1(4670.17,937) 1(4670.17,937) 1(4670.17,943) 1(4670.17,943) 1(4670.17,946) 1(4670.17,946) 1(4673.38,700.79) 1(4673.38,700.79) 1(4673.38,705.79) 1(4673.38,705.79) 1(4673.38,715.79) 1(4673.38,715.79) 1(4673.38,720.79) 1(4673.38,720.79) 1(4674.17,470) 1(4674.17,470) 1(4674.17,475) 1(4674.17,475) 1(4674.17,485) 1(4674.17,485) 1(4674.17,490) 1(4674.17,490) 1(4674.17,930) 1(4674.17,930) 1(4674.17,935) 1(4674.17,935) 1(4674.17,945) 1(4674.17,945) 1(4674.17,950) 1(4674.17,950) 1(4691.93,2240) 1(4691.93,2244) 1(4691.93,2256) 1(4691.93,2260) 1(4692.74,38.88) 1(4692.74,42.88) 1(4692.74,54.88) 1(4692.74,58.88) 1(4693.02,549.17) 1(4693.02,549.17) 1(4693.02,554.17) 1(4693.02,554.17) 1(4693.02,564.17) 1(4693.02,564.17) 1(4693.02,569.17) 1(4693.02,569.17) 1(4693.02,1060) 1(4693.02,1060) 1(4693.02,1065) 1(4693.02,1065) 1(4693.02,1075) 1(4693.02,1075) 1(4693.02,1080) 1(4693.02,1080) 1(4694.01,780.16) 1(4694.01,780.16) 1(4694.01,785.16) 1(4694.01,785.16) 1(4694.01,795.16) 1(4694.01,795.16) 1(4694.01,800.16) 1(4694.01,800.16) 1(4694.17,240) 1(4694.17,240) 1(4694.17,260) 1(4694.17,260) 1(4694.17,340) 1(4694.17,340) 1(4694.17,360) 1(4694.17,360) 1(4694.17,1940) 1(4694.17,1940) 1(4694.17,1960) 1(4694.17,1960) 1(4694.17,2040) 1(4694.17,2040) 1(4694.17,2060) 1(4694.17,2060) 1(4697.02,553.17) 1(4697.02,553.17) 1(4697.02,556.17) 1(4697.02,556.17) 1(4697.02,562.17) 1(4697.02,562.17) 1(4697.02,565.17) 1(4697.02,565.17) 1(4697.02,1064) 1(4697.02,1064) 1(4697.02,1067) 1(4697.02,1067) 1(4697.02,1073) 1(4697.02,1073) 1(4697.02,1076) 1(4697.02,1076) 1(4698.01,784.16) 1(4698.01,784.16) 1(4698.01,787.16) 1(4698.01,787.16) 1(4698.01,793.16) 1(4698.01,793.16) 1(4698.01,796.16) 1(4698.01,796.16) 1(4698.02,549.17) 1(4698.02,549.17) 1(4698.02,559.17) 1(4698.02,559.17) 1(4698.02,569.17) 1(4698.02,569.17) 1(4698.02,1060) 1(4698.02,1060) 1(4698.02,1070) 1(4698.02,1070) 1(4698.02,1080) 1(4698.02,1080) 1(4698.17,244) 1(4698.17,244) 1(4698.17,256) 1(4698.17,256) 1(4698.17,344) 1(4698.17,344) 1(4698.17,356) 1(4698.17,356) 1(4698.17,1944) 1(4698.17,1944) 1(4698.17,1956) 1(4698.17,1956) 1(4698.17,2044) 1(4698.17,2044) 1(4698.17,2056) 1(4698.17,2056) 1(4699.01,780.16) 1(4699.01,780.16) 1(4699.01,790.16) 1(4699.01,790.16) 1(4699.01,800.16) 1(4699.01,800.16) 1(4700.02,553.17) 1(4700.02,553.17) 1(4700.02,559.17) 1(4700.02,559.17) 1(4700.02,565.17) 1(4700.02,565.17) 1(4700.02,1064) 1(4700.02,1064) 1(4700.02,1070) 1(4700.02,1070) 1(4700.02,1076) 1(4700.02,1076) 1(4701.01,784.16) 1(4701.01,784.16) 1(4701.01,790.16) 1(4701.01,790.16) 1(4701.01,796.16) 1(4701.01,796.16) 1(4703.02,554.17) 1(4703.02,554.17) 1(4703.02,556.17) 1(4703.02,556.17) 1(4703.02,562.17) 1(4703.02,562.17) 1(4703.02,564.17) 1(4703.02,564.17) 1(4703.02,1065) 1(4703.02,1065) 1(4703.02,1067) 1(4703.02,1067) 1(4703.02,1073) 1(4703.02,1073) 1(4703.02,1075) 1(4703.02,1075) 1(4703.85,1009.68) 1(4703.85,1013.68) 1(4703.85,1025.68) 1(4703.85,1029.68) 1(4704.01,785.16) 1(4704.01,785.16) 1(4704.01,787.16) 1(4704.01,787.16) 1(4704.01,793.16) 1(4704.01,793.16) 1(4704.01,795.16) 1(4704.01,795.16) 1(4706.02,553.17) 1(4706.02,553.17) 1(4706.02,559.17) 1(4706.02,559.17) 1(4706.02,565.17) 1(4706.02,565.17) 1(4706.02,1064) 1(4706.02,1064) 1(4706.02,1070) 1(4706.02,1070) 1(4706.02,1076) 1(4706.02,1076) 1(4707.01,784.16) 1(4707.01,784.16) 1(4707.01,790.16) 1(4707.01,790.16) 1(4707.01,796.16) 1(4707.01,796.16) 1(4708.02,549.17) 1(4708.02,549.17) 1(4708.02,559.17) 1(4708.02,559.17) 1(4708.02,569.17) 1(4708.02,569.17) 1(4708.02,1060) 1(4708.02,1060) 1(4708.02,1070) 1(4708.02,1070) 1(4708.02,1080) 1(4708.02,1080) 1(4709.01,780.16) 1(4709.01,780.16) 1(4709.01,790.16) 1(4709.01,790.16) 1(4709.01,800.16) 1(4709.01,800.16) 1(4709.02,553.17) 1(4709.02,553.17) 1(4709.02,556.17) 1(4709.02,556.17) 1(4709.02,562.17) 1(4709.02,562.17) 1(4709.02,565.17) 1(4709.02,565.17) 1(4709.02,1064) 1(4709.02,1064) 1(4709.02,1067) 1(4709.02,1067) 1(4709.02,1073) 1(4709.02,1073) 1(4709.02,1076) 1(4709.02,1076) 1(4710.01,784.16) 1(4710.01,784.16) 1(4710.01,787.16) 1(4710.01,787.16) 1(4710.01,793.16) 1(4710.01,793.16) 1(4710.01,796.16) 1(4710.01,796.16) 1(4710.17,244) 1(4710.17,244) 1(4710.17,256) 1(4710.17,256) 1(4710.17,344) 1(4710.17,344) 1(4710.17,356) 1(4710.17,356) 1(4710.17,1944) 1(4710.17,1944) 1(4710.17,1956) 1(4710.17,1956) 1(4710.17,2044) 1(4710.17,2044) 1(4710.17,2056) 1(4710.17,2056) 1(4713.02,549.17) 1(4713.02,549.17) 1(4713.02,554.17) 1(4713.02,554.17) 1(4713.02,564.17) 1(4713.02,564.17) 1(4713.02,569.17) 1(4713.02,569.17) 1(4713.02,1060) 1(4713.02,1060) 1(4713.02,1065) 1(4713.02,1065) 1(4713.02,1075) 1(4713.02,1075) 1(4713.02,1080) 1(4713.02,1080) 1(4714.01,780.16) 1(4714.01,780.16) 1(4714.01,785.16) 1(4714.01,785.16) 1(4714.01,795.16) 1(4714.01,795.16) 1(4714.01,800.16) 1(4714.01,800.16) 1(4714.17,240) 1(4714.17,240) 1(4714.17,260) 1(4714.17,260) 1(4714.17,340) 1(4714.17,340) 1(4714.17,360) 1(4714.17,360) 1(4714.17,667.01) 1(4714.17,667.01) 1(4714.17,672.01) 1(4714.17,672.01) 1(4714.17,682.01) 1(4714.17,682.01) 1(4714.17,687.01) 1(4714.17,687.01) 1(4714.17,904.02) 1(4714.17,904.02) 1(4714.17,909.02) 1(4714.17,909.02) 1(4714.17,919.02) 1(4714.17,919.02) 1(4714.17,924.02) 1(4714.17,924.02) 1(4714.17,1940) 1(4714.17,1940) 1(4714.17,1960) 1(4714.17,1960) 1(4714.17,2040) 1(4714.17,2040) 1(4714.17,2060) 1(4714.17,2060) 1(4718.17,671.01) 1(4718.17,671.01) 1(4718.17,674.01) 1(4718.17,674.01) 1(4718.17,680.01) 1(4718.17,680.01) 1(4718.17,683.01) 1(4718.17,683.01) 1(4718.17,908.02) 1(4718.17,908.02) 1(4718.17,911.02) 1(4718.17,911.02) 1(4718.17,917.02) 1(4718.17,917.02) 1(4718.17,920.02) 1(4718.17,920.02) 1(4719.17,667.01) 1(4719.17,667.01) 1(4719.17,677.01) 1(4719.17,677.01) 1(4719.17,687.01) 1(4719.17,687.01) 1(4719.17,904.02) 1(4719.17,904.02) 1(4719.17,914.02) 1(4719.17,914.02) 1(4719.17,924.02) 1(4719.17,924.02) 1(4721.17,671.01) 1(4721.17,671.01) 1(4721.17,677.01) 1(4721.17,677.01) 1(4721.17,683.01) 1(4721.17,683.01) 1(4721.17,908.02) 1(4721.17,908.02) 1(4721.17,914.02) 1(4721.17,914.02) 1(4721.17,920.02) 1(4721.17,920.02) 1(4724.17,672.01) 1(4724.17,672.01) 1(4724.17,674.01) 1(4724.17,674.01) 1(4724.17,680.01) 1(4724.17,680.01) 1(4724.17,682.01) 1(4724.17,682.01) 1(4724.17,909.02) 1(4724.17,909.02) 1(4724.17,911.02) 1(4724.17,911.02) 1(4724.17,917.02) 1(4724.17,917.02) 1(4724.17,919.02) 1(4724.17,919.02) 1(4727.17,671.01) 1(4727.17,671.01) 1(4727.17,677.01) 1(4727.17,677.01) 1(4727.17,683.01) 1(4727.17,683.01) 1(4727.17,908.02) 1(4727.17,908.02) 1(4727.17,914.02) 1(4727.17,914.02) 1(4727.17,920.02) 1(4727.17,920.02) 1(4729.17,667.01) 1(4729.17,667.01) 1(4729.17,677.01) 1(4729.17,677.01) 1(4729.17,687.01) 1(4729.17,687.01) 1(4729.17,904.02) 1(4729.17,904.02) 1(4729.17,914.02) 1(4729.17,914.02) 1(4729.17,924.02) 1(4729.17,924.02) 1(4729.17,1605) 1(4729.17,1605) 1(4729.17,1610) 1(4729.17,1610) 1(4729.17,1620) 1(4729.17,1620) 1(4729.17,1625) 1(4729.17,1625) 1(4730.17,671.01) 1(4730.17,671.01) 1(4730.17,674.01) 1(4730.17,674.01) 1(4730.17,680.01) 1(4730.17,680.01) 1(4730.17,683.01) 1(4730.17,683.01) 1(4730.17,908.02) 1(4730.17,908.02) 1(4730.17,911.02) 1(4730.17,911.02) 1(4730.17,917.02) 1(4730.17,917.02) 1(4730.17,920.02) 1(4730.17,920.02) 1(4730.74,1370) 1(4730.74,1370) 1(4730.74,1375) 1(4730.74,1375) 1(4730.74,1385) 1(4730.74,1385) 1(4730.74,1390) 1(4730.74,1390) 1(4733.17,1609) 1(4733.17,1609) 1(4733.17,1612) 1(4733.17,1612) 1(4733.17,1618) 1(4733.17,1618) 1(4733.17,1621) 1(4733.17,1621) 1(4734.17,667.01) 1(4734.17,667.01) 1(4734.17,672.01) 1(4734.17,672.01) 1(4734.17,682.01) 1(4734.17,682.01) 1(4734.17,687.01) 1(4734.17,687.01) 1(4734.17,904.02) 1(4734.17,904.02) 1(4734.17,909.02) 1(4734.17,909.02) 1(4734.17,919.02) 1(4734.17,919.02) 1(4734.17,924.02) 1(4734.17,924.02) 1(4734.17,1605) 1(4734.17,1605) 1(4734.17,1615) 1(4734.17,1615) 1(4734.17,1625) 1(4734.17,1625) 1(4734.74,1374) 1(4734.74,1374) 1(4734.74,1377) 1(4734.74,1377) 1(4734.74,1383) 1(4734.74,1383) 1(4734.74,1386) 1(4734.74,1386) 1(4735.74,1370) 1(4735.74,1370) 1(4735.74,1380) 1(4735.74,1380) 1(4735.74,1390) 1(4735.74,1390) 1(4736.17,1609) 1(4736.17,1609) 1(4736.17,1615) 1(4736.17,1615) 1(4736.17,1621) 1(4736.17,1621) 1(4737.74,1374) 1(4737.74,1374) 1(4737.74,1380) 1(4737.74,1380) 1(4737.74,1386) 1(4737.74,1386) 1(4739.17,1610) 1(4739.17,1610) 1(4739.17,1612) 1(4739.17,1612) 1(4739.17,1618) 1(4739.17,1618) 1(4739.17,1620) 1(4739.17,1620) 1(4740.74,1375) 1(4740.74,1375) 1(4740.74,1377) 1(4740.74,1377) 1(4740.74,1383) 1(4740.74,1383) 1(4740.74,1385) 1(4740.74,1385) 1(4742.17,1609) 1(4742.17,1609) 1(4742.17,1615) 1(4742.17,1615) 1(4742.17,1621) 1(4742.17,1621) 1(4743.74,1374) 1(4743.74,1374) 1(4743.74,1380) 1(4743.74,1380) 1(4743.74,1386) 1(4743.74,1386) 1(4744.17,1495) 1(4744.17,1495) 1(4744.17,1505) 1(4744.17,1505) 1(4744.17,1605) 1(4744.17,1605) 1(4744.17,1615) 1(4744.17,1615) 1(4744.17,1625) 1(4744.17,1625) 1(4745.17,1609) 1(4745.17,1609) 1(4745.17,1612) 1(4745.17,1612) 1(4745.17,1618) 1(4745.17,1618) 1(4745.17,1621) 1(4745.17,1621) 1(4745.74,1370) 1(4745.74,1370) 1(4745.74,1380) 1(4745.74,1380) 1(4745.74,1390) 1(4745.74,1390) 1(4746.74,1374) 1(4746.74,1374) 1(4746.74,1377) 1(4746.74,1377) 1(4746.74,1383) 1(4746.74,1383) 1(4746.74,1386) 1(4746.74,1386) 1(4749.17,1490) 1(4749.17,1490) 1(4749.17,1495) 1(4749.17,1495) 1(4749.17,1505) 1(4749.17,1505) 1(4749.17,1510) 1(4749.17,1510) 1(4749.17,1605) 1(4749.17,1605) 1(4749.17,1610) 1(4749.17,1610) 1(4749.17,1620) 1(4749.17,1620) 1(4749.17,1625) 1(4749.17,1625) 1(4750.74,1370) 1(4750.74,1370) 1(4750.74,1375) 1(4750.74,1375) 1(4750.74,1385) 1(4750.74,1385) 1(4750.74,1390) 1(4750.74,1390) 1(4759.17,1490) 1(4759.17,1490) 1(4759.17,1495) 1(4759.17,1495) 1(4759.17,1505) 1(4759.17,1505) 1(4759.17,1510) 1(4759.17,1510) 1(4764.17,1495) 1(4764.17,1495) 1(4764.17,1505) 1(4764.17,1505) 1(4780.55,590.78) 1(4780.55,590.78) 1(4780.55,595.78) 1(4780.55,595.78) 1(4780.55,605.78) 1(4780.55,605.78) 1(4780.55,610.78) 1(4780.55,610.78) 1(4780.55,1050) 1(4780.55,1050) 1(4780.55,1055) 1(4780.55,1055) 1(4780.55,1065) 1(4780.55,1065) 1(4780.55,1070) 1(4780.55,1070) 1(4784.17,821.38) 1(4784.17,821.38) 1(4784.17,826.38) 1(4784.17,826.38) 1(4784.17,836.38) 1(4784.17,836.38) 1(4784.17,841.38) 1(4784.17,841.38) 1(4784.55,594.78) 1(4784.55,594.78) 1(4784.55,597.78) 1(4784.55,597.78) 1(4784.55,603.78) 1(4784.55,603.78) 1(4784.55,606.78) 1(4784.55,606.78) 1(4784.55,1054) 1(4784.55,1054) 1(4784.55,1057) 1(4784.55,1057) 1(4784.55,1063) 1(4784.55,1063) 1(4784.55,1066) 1(4784.55,1066) 1(4785.55,590.78) 1(4785.55,590.78) 1(4785.55,600.78) 1(4785.55,600.78) 1(4785.55,610.78) 1(4785.55,610.78) 1(4785.55,1050) 1(4785.55,1050) 1(4785.55,1060) 1(4785.55,1060) 1(4785.55,1070) 1(4785.55,1070) 1(4787.55,594.78) 1(4787.55,594.78) 1(4787.55,600.78) 1(4787.55,600.78) 1(4787.55,606.78) 1(4787.55,606.78) 1(4787.55,1054) 1(4787.55,1054) 1(4787.55,1060) 1(4787.55,1060) 1(4787.55,1066) 1(4787.55,1066) 1(4788.17,825.38) 1(4788.17,825.38) 1(4788.17,828.38) 1(4788.17,828.38) 1(4788.17,834.38) 1(4788.17,834.38) 1(4788.17,837.38) 1(4788.17,837.38) 1(4789.17,821.38) 1(4789.17,821.38) 1(4789.17,831.38) 1(4789.17,831.38) 1(4789.17,841.38) 1(4789.17,841.38) 1(4790.55,595.78) 1(4790.55,595.78) 1(4790.55,597.78) 1(4790.55,597.78) 1(4790.55,603.78) 1(4790.55,603.78) 1(4790.55,605.78) 1(4790.55,605.78) 1(4790.55,1055) 1(4790.55,1055) 1(4790.55,1057) 1(4790.55,1057) 1(4790.55,1063) 1(4790.55,1063) 1(4790.55,1065) 1(4790.55,1065) 1(4791.17,825.38) 1(4791.17,825.38) 1(4791.17,831.38) 1(4791.17,831.38) 1(4791.17,837.38) 1(4791.17,837.38) 1(4793.55,594.78) 1(4793.55,594.78) 1(4793.55,600.78) 1(4793.55,600.78) 1(4793.55,606.78) 1(4793.55,606.78) 1(4793.55,1054) 1(4793.55,1054) 1(4793.55,1060) 1(4793.55,1060) 1(4793.55,1066) 1(4793.55,1066) 1(4794.17,240) 1(4794.17,240) 1(4794.17,260) 1(4794.17,260) 1(4794.17,340) 1(4794.17,340) 1(4794.17,360) 1(4794.17,360) 1(4794.17,826.38) 1(4794.17,826.38) 1(4794.17,828.38) 1(4794.17,828.38) 1(4794.17,834.38) 1(4794.17,834.38) 1(4794.17,836.38) 1(4794.17,836.38) 1(4794.17,1940) 1(4794.17,1940) 1(4794.17,1960) 1(4794.17,1960) 1(4794.17,2040) 1(4794.17,2040) 1(4794.17,2060) 1(4794.17,2060) 1(4795.55,590.78) 1(4795.55,590.78) 1(4795.55,600.78) 1(4795.55,600.78) 1(4795.55,610.78) 1(4795.55,610.78) 1(4795.55,1050) 1(4795.55,1050) 1(4795.55,1060) 1(4795.55,1060) 1(4795.55,1070) 1(4795.55,1070) 1(4796.55,594.78) 1(4796.55,594.78) 1(4796.55,597.78) 1(4796.55,597.78) 1(4796.55,603.78) 1(4796.55,603.78) 1(4796.55,606.78) 1(4796.55,606.78) 1(4796.55,1054) 1(4796.55,1054) 1(4796.55,1057) 1(4796.55,1057) 1(4796.55,1063) 1(4796.55,1063) 1(4796.55,1066) 1(4796.55,1066) 1(4797.17,825.38) 1(4797.17,825.38) 1(4797.17,831.38) 1(4797.17,831.38) 1(4797.17,837.38) 1(4797.17,837.38) 1(4798.17,244) 1(4798.17,244) 1(4798.17,256) 1(4798.17,256) 1(4798.17,344) 1(4798.17,344) 1(4798.17,356) 1(4798.17,356) 1(4798.17,1944) 1(4798.17,1944) 1(4798.17,1956) 1(4798.17,1956) 1(4798.17,2044) 1(4798.17,2044) 1(4798.17,2056) 1(4798.17,2056) 1(4799.17,821.38) 1(4799.17,821.38) 1(4799.17,831.38) 1(4799.17,831.38) 1(4799.17,841.38) 1(4799.17,841.38) 1(4800.17,825.38) 1(4800.17,825.38) 1(4800.17,828.38) 1(4800.17,828.38) 1(4800.17,834.38) 1(4800.17,834.38) 1(4800.17,837.38) 1(4800.17,837.38) 1(4800.55,590.78) 1(4800.55,590.78) 1(4800.55,595.78) 1(4800.55,595.78) 1(4800.55,605.78) 1(4800.55,605.78) 1(4800.55,610.78) 1(4800.55,610.78) 1(4800.55,1050) 1(4800.55,1050) 1(4800.55,1055) 1(4800.55,1055) 1(4800.55,1065) 1(4800.55,1065) 1(4800.55,1070) 1(4800.55,1070) 1(4804.17,821.38) 1(4804.17,821.38) 1(4804.17,826.38) 1(4804.17,826.38) 1(4804.17,836.38) 1(4804.17,836.38) 1(4804.17,841.38) 1(4804.17,841.38) 1(4809.17,895) 1(4809.17,895) 1(4809.17,905) 1(4809.17,905) 1(4810.17,244) 1(4810.17,244) 1(4810.17,256) 1(4810.17,256) 1(4810.17,344) 1(4810.17,344) 1(4810.17,356) 1(4810.17,356) 1(4810.17,1944) 1(4810.17,1944) 1(4810.17,1956) 1(4810.17,1956) 1(4810.17,2044) 1(4810.17,2044) 1(4810.17,2056) 1(4810.17,2056) 1(4814.17,240) 1(4814.17,240) 1(4814.17,260) 1(4814.17,260) 1(4814.17,340) 1(4814.17,340) 1(4814.17,360) 1(4814.17,360) 1(4814.17,890) 1(4814.17,890) 1(4814.17,895) 1(4814.17,895) 1(4814.17,905) 1(4814.17,905) 1(4814.17,910) 1(4814.17,910) 1(4814.17,1940) 1(4814.17,1940) 1(4814.17,1960) 1(4814.17,1960) 1(4814.17,2040) 1(4814.17,2040) 1(4814.17,2060) 1(4814.17,2060) 1(4824.17,890) 1(4824.17,890) 1(4824.17,895) 1(4824.17,895) 1(4824.17,905) 1(4824.17,905) 1(4824.17,910) 1(4824.17,910) 1(4827.79,1050) 1(4827.79,1050) 1(4827.79,1055) 1(4827.79,1055) 1(4827.79,1065) 1(4827.79,1065) 1(4827.79,1070) 1(4827.79,1070) 1(4828.58,590.78) 1(4828.58,590.78) 1(4828.58,595.78) 1(4828.58,595.78) 1(4828.58,605.78) 1(4828.58,605.78) 1(4828.58,610.78) 1(4828.58,610.78) 1(4828.58,820.79) 1(4828.58,820.79) 1(4828.58,825.79) 1(4828.58,825.79) 1(4828.58,835.79) 1(4828.58,835.79) 1(4828.58,840.79) 1(4828.58,840.79) 1(4829.17,895) 1(4829.17,895) 1(4829.17,905) 1(4829.17,905) 1(4831.79,1054) 1(4831.79,1054) 1(4831.79,1057) 1(4831.79,1057) 1(4831.79,1063) 1(4831.79,1063) 1(4831.79,1066) 1(4831.79,1066) 1(4832.58,594.78) 1(4832.58,594.78) 1(4832.58,597.78) 1(4832.58,597.78) 1(4832.58,603.78) 1(4832.58,603.78) 1(4832.58,606.78) 1(4832.58,606.78) 1(4832.58,824.79) 1(4832.58,824.79) 1(4832.58,827.79) 1(4832.58,827.79) 1(4832.58,833.79) 1(4832.58,833.79) 1(4832.58,836.79) 1(4832.58,836.79) 1(4832.79,1050) 1(4832.79,1050) 1(4832.79,1060) 1(4832.79,1060) 1(4832.79,1070) 1(4832.79,1070) 1(4833.58,590.78) 1(4833.58,590.78) 1(4833.58,600.78) 1(4833.58,600.78) 1(4833.58,610.78) 1(4833.58,610.78) 1(4833.58,820.79) 1(4833.58,820.79) 1(4833.58,830.79) 1(4833.58,830.79) 1(4833.58,840.79) 1(4833.58,840.79) 1(4834.17,1525) 1(4834.17,1525) 1(4834.17,1530) 1(4834.17,1530) 1(4834.17,1540) 1(4834.17,1540) 1(4834.17,1545) 1(4834.17,1545) 1(4834.32,1454.06) 1(4834.32,1454.06) 1(4834.32,1459.06) 1(4834.32,1459.06) 1(4834.32,1469.06) 1(4834.32,1469.06) 1(4834.32,1474.06) 1(4834.32,1474.06) 1(4834.79,1054) 1(4834.79,1054) 1(4834.79,1060) 1(4834.79,1060) 1(4834.79,1066) 1(4834.79,1066) 1(4835.58,594.78) 1(4835.58,594.78) 1(4835.58,600.78) 1(4835.58,600.78) 1(4835.58,606.78) 1(4835.58,606.78) 1(4835.58,824.79) 1(4835.58,824.79) 1(4835.58,830.79) 1(4835.58,830.79) 1(4835.58,836.79) 1(4835.58,836.79) 1(4836.42,1365) 1(4836.42,1365) 1(4836.42,1370) 1(4836.42,1370) 1(4836.42,1380) 1(4836.42,1380) 1(4836.42,1385) 1(4836.42,1385) 1(4837.79,1055) 1(4837.79,1055) 1(4837.79,1057) 1(4837.79,1057) 1(4837.79,1063) 1(4837.79,1063) 1(4837.79,1065) 1(4837.79,1065) 1(4838.17,1529) 1(4838.17,1529) 1(4838.17,1532) 1(4838.17,1532) 1(4838.17,1538) 1(4838.17,1538) 1(4838.17,1541) 1(4838.17,1541) 1(4838.32,1458.06) 1(4838.32,1458.06) 1(4838.32,1461.06) 1(4838.32,1461.06) 1(4838.32,1467.06) 1(4838.32,1467.06) 1(4838.32,1470.06) 1(4838.32,1470.06) 1(4838.58,595.78) 1(4838.58,595.78) 1(4838.58,597.78) 1(4838.58,597.78) 1(4838.58,603.78) 1(4838.58,603.78) 1(4838.58,605.78) 1(4838.58,605.78) 1(4838.58,825.79) 1(4838.58,825.79) 1(4838.58,827.79) 1(4838.58,827.79) 1(4838.58,833.79) 1(4838.58,833.79) 1(4838.58,835.79) 1(4838.58,835.79) 1(4839.17,1525) 1(4839.17,1525) 1(4839.17,1535) 1(4839.17,1535) 1(4839.17,1545) 1(4839.17,1545) 1(4839.32,1454.06) 1(4839.32,1454.06) 1(4839.32,1464.06) 1(4839.32,1464.06) 1(4839.32,1474.06) 1(4839.32,1474.06) 1(4840.42,1369) 1(4840.42,1369) 1(4840.42,1372) 1(4840.42,1372) 1(4840.42,1378) 1(4840.42,1378) 1(4840.42,1381) 1(4840.42,1381) 1(4840.79,1054) 1(4840.79,1054) 1(4840.79,1060) 1(4840.79,1060) 1(4840.79,1066) 1(4840.79,1066) 1(4841.17,1529) 1(4841.17,1529) 1(4841.17,1535) 1(4841.17,1535) 1(4841.17,1541) 1(4841.17,1541) 1(4841.32,1458.06) 1(4841.32,1458.06) 1(4841.32,1464.06) 1(4841.32,1464.06) 1(4841.32,1470.06) 1(4841.32,1470.06) 1(4841.42,1365) 1(4841.42,1365) 1(4841.42,1375) 1(4841.42,1375) 1(4841.42,1385) 1(4841.42,1385) 1(4841.58,594.78) 1(4841.58,594.78) 1(4841.58,600.78) 1(4841.58,600.78) 1(4841.58,606.78) 1(4841.58,606.78) 1(4841.58,824.79) 1(4841.58,824.79) 1(4841.58,830.79) 1(4841.58,830.79) 1(4841.58,836.79) 1(4841.58,836.79)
